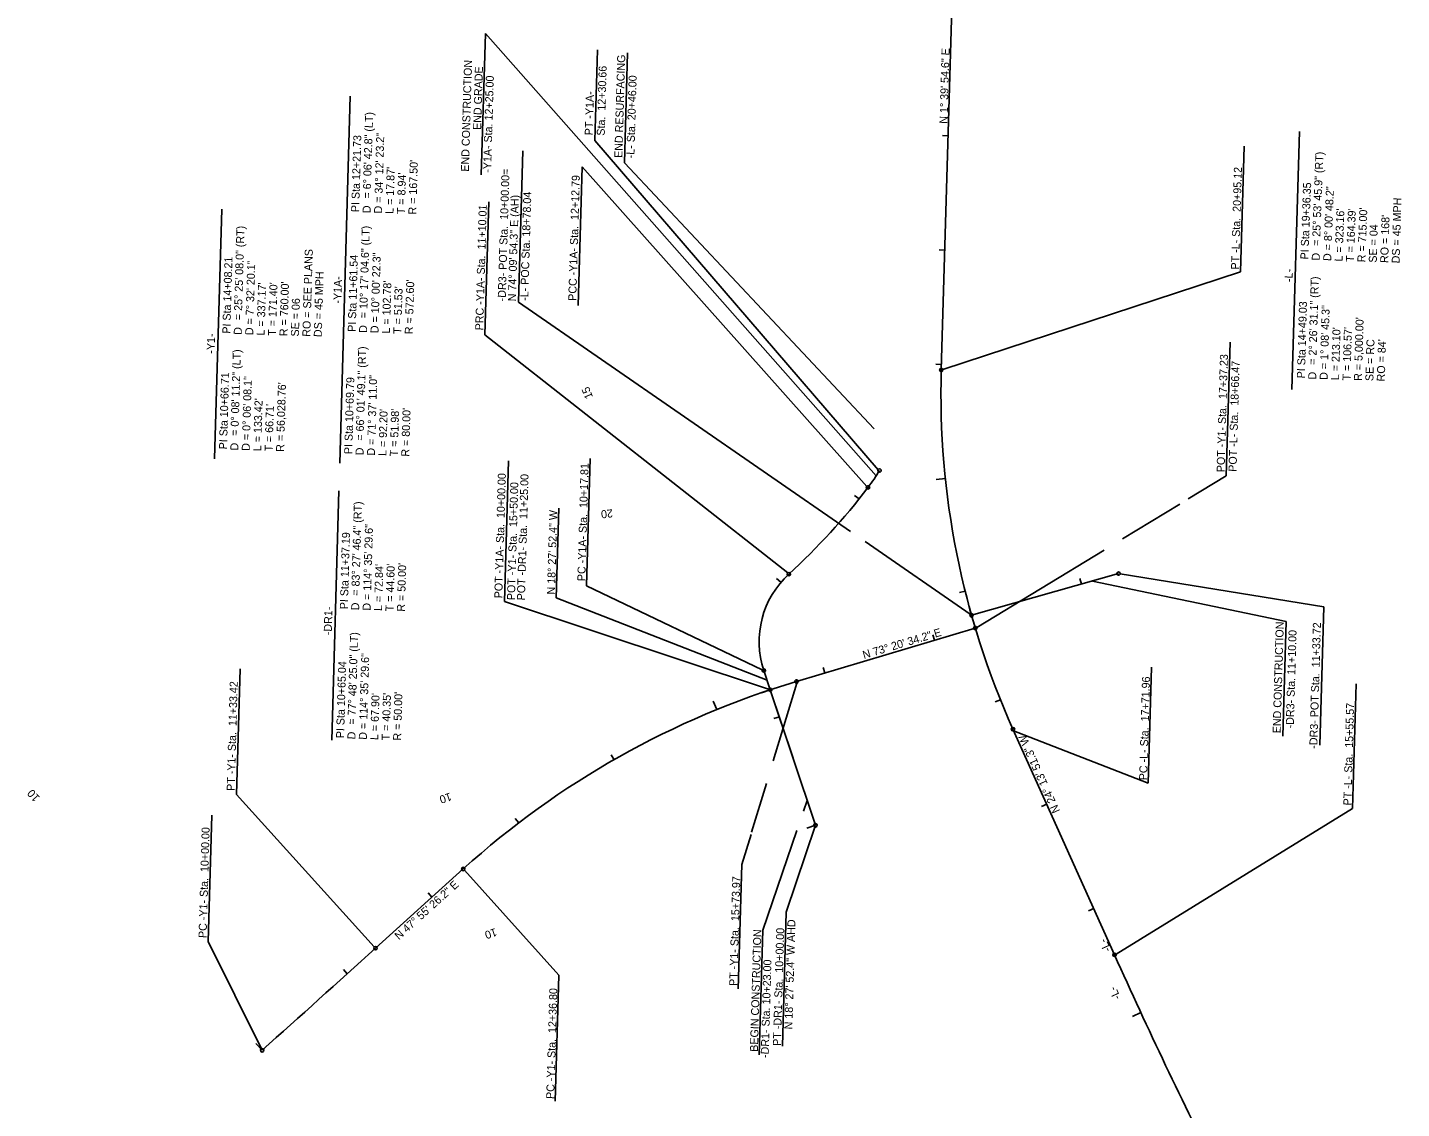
# Model space of a CAD drawing. Extents: x 2096901 to 2098386, y 684661 to 689731.
# Drawn here: x 2096901 to 2098103, y 685468 to 686414 of the extents above; entities that cross this region are included whole.
import ezdxf

# ---------------------------------------------------------------- set-up
doc = ezdxf.new("R2010")
doc.units = 0
for name, color, linetype in [('Prop Horizontal Alignment', 7, 'Continuous'), ('Prop Horizontal Alignment Curve and Spiral Data', 7, 'Continuous'), ('Prop Horizontal Alignment Direction Label', 7, 'Continuous'), ('Prop Horizontal Alignment Station Label', 7, 'Continuous'), ('Prop Horizontal Alignment Tick Label', 7, 'Continuous'), ('Prop Horizontal Alignment Tick Large', 7, 'Continuous'), ('Prop Horizontal Alignment Tick Small', 7, 'Continuous'), ('Scratch_Level_3', 7, 'Continuous'), ('Scratch_Level_5', 7, 'Continuous'), ('Scratch_Level_6', 7, 'Continuous'), ('Scratch_Level_8', 7, 'Continuous')]:
    doc.layers.add(name, color=color, linetype=linetype)

msp = doc.modelspace()

# ---------------------------------------------------------------- linework, layer by layer
at = {"layer": 'Prop Horizontal Alignment'}
for p, q in [((2097700.4, 686114.2), (2097723.2, 686897.8)), ((2097726.9, 685899.6), (2097855.5, 685936.1)), ((2097573.7, 685841.7), (2097730.1, 685888.5)), ((2097550.8, 685834.5), (2097545.2, 685851.4)), ((2097590.4, 685715.9), (2097550.8, 685834.5)), ((2097851.9, 685602.7), (2097763.1, 685800)), ((2097205.5, 685608.4), (2097282.3, 685677.7))]:
    msp.add_line(p, q, dxfattribs=at)
for centre, radius, start, end in [((2098415.1, 686093.4), 715, 178.3348, 204.2309), ((2097503.1, 686113), 167.5, 322.7189, 328.8307), ((2097180.7, 686358.3), 572.6, 312.4342, 322.7189), ((2097621.1, 685876.7), 80, 132.4342, 198.4646), ((2097791.5, 685113.6), 760, 106.6572, 132.076), ((2059659.7, 727196.1), 56028.8, 311.9396, 312.07604), ((2102411.4, 687654.7), 5000, 204.2309, 206.6729)]:
    msp.add_arc(centre, radius, start, end, dxfattribs=at)
at = {"layer": 'Prop Horizontal Alignment Curve and Spiral Data'}
for p, q in [((2097174.2, 686032.6), (2097183.5, 686353.6)), ((2098007, 686097.1), (2098013.6, 686322.8)), ((2097064.7, 686036.6), (2097071, 686254.8)), ((2097167.2, 685790.3), (2097173.5, 686008.5))]:
    msp.add_line(p, q, dxfattribs=at)
at = {"layer": 'Prop Horizontal Alignment Station Label'}
for p, q in [((2097298, 686285), (2097301.6, 686408.7)), ((2097643.4, 686021.5), (2097301.6, 686408.7)), ((2097397.3, 686315), (2097399.6, 686394.2)), ((2097423.2, 686295.3), (2097426, 686391.6)), ((2097645.1, 686027), (2097397.3, 686315)), ((2097330.7, 686173.6), (2097334.5, 686306)), ((2097962, 686200), (2097965.2, 686309.9)), ((2097382.9, 686170.5), (2097386.4, 686292)), ((2097635.2, 686012.4), (2097386.4, 686292)), ((2097641.8, 686062.8), (2097423.2, 686295.3)), ((2097301.2, 686144.9), (2097304.6, 686261.3)), ((2097701.8, 686114.6), (2097962, 686200)), ((2097621.1, 685973), (2097330.7, 686173.6)), ((2097566.1, 685936.8), (2097301.2, 686144.9)), ((2097953.1, 686138.6), (2097949.7, 686021.6)), ((2097318.4, 685911.6), (2097322, 686034.6)), ((2097390.2, 685925.5), (2097393.4, 686036.9)), ((2097916.4, 686001.4), (2097949.7, 686021.6)), ((2097363.7, 685915), (2097366, 685993.3)), ((2097858.9, 685966.4), (2097909, 685996.9)), ((2097725.8, 685900.7), (2097633.7, 685964.3)), ((2097731.5, 685889), (2097842.9, 685956.7)), ((2097857, 685935.8), (2098034.9, 685907.1)), ((2097543.8, 685852), (2097390.2, 685925.5)), ((2098002, 685894.1), (2097832.7, 685929.6)), ((2097549.4, 685835), (2097318.4, 685911.6)), ((2097548, 685842.9), (2097363.7, 685915)), ((2098031.4, 685786.1), (2098034.9, 685907.1)), ((2097999.1, 685794), (2098002, 685894.1)), ((2097084, 685743), (2097087.2, 685852.9)), ((2097881.4, 685752.7), (2097884.4, 685854.2)), ((2097574.1, 685840.3), (2097553.5, 685772.2)), ((2098060.2, 685730.7), (2098063.3, 685839.7)), ((2097762, 685799), (2097881.4, 685752.7)), ((2097547.5, 685752.5), (2097534.5, 685709.8)), ((2097204.5, 685609.5), (2097084, 685743)), ((2097583.1, 685737.7), (2097579.9, 685728.2)), ((2097853.3, 685603.3), (2098060.2, 685730.7)), ((2097062.3, 685724.7), (2097059.1, 685614.2)), ((2097590.4, 685715.9), (2097564.8, 685639.9)), ((2097534, 685708), (2097526, 685681.7)), ((2097574.1, 685711.4), (2097544.4, 685624.3)), ((2097526, 685681.7), (2097522.8, 685572.8)), ((2097283.3, 685676.6), (2097366, 685584.9)), ((2097561.4, 685522.6), (2097564.8, 685639.9)), ((2097541.2, 685515.2), (2097544.4, 685624.3)), ((2097105.9, 685520.5), (2097059.1, 685614.2)), ((2097366, 685584.9), (2097362.8, 685474.5))]:
    msp.add_line(p, q, dxfattribs=at)
for centre in [(2097700.4, 686114.2), (2097646.4, 686026.3), (2097636.3, 686011.5), (2097567.1, 685935.7), (2097855.5, 685936.1), (2097855.5, 685936.1), (2097726.9, 685899.6), (2097726.9, 685899.6), (2097730.1, 685888.5), (2097545.2, 685851.4), (2097550.8, 685834.5), (2097550.8, 685834.5), (2097550.8, 685834.5), (2097573.7, 685841.7), (2097763.1, 685800), (2097590.4, 685715.9), (2097282.3, 685677.7), (2097205.5, 685608.4), (2097851.9, 685602.7), (2097106.4, 685519.1)]:
    msp.add_circle(centre, 1.5, dxfattribs=at)
at = {"layer": 'Prop Horizontal Alignment Tick Large'}
for p, q in [((2097704, 686019.2), (2097696, 686018.4)), ((2097726.9, 685899.6), (2097724.7, 685907.3)), ((2097550.8, 685834.5), (2097543.3, 685831.9)), ((2097504, 685817.1), (2097500.9, 685824.5)), ((2097590.4, 685715.9), (2097582.8, 685713.4)), ((2097875, 685552.1), (2097867.7, 685548.8)), ((2097106.4, 685519.1), (2097101, 685525.1))]:
    msp.add_line(p, q, dxfattribs=at)
at = {"layer": 'Prop Horizontal Alignment Tick Small'}
for p, q in [((2097706.4, 686319), (2097701.4, 686319.2)), ((2097703.5, 686219.1), (2097698.5, 686219.2)), ((2097700.5, 686119.1), (2097695.6, 686119.2)), ((2097628.5, 686001.4), (2097624.6, 686004.5)), ((2097560.2, 685928.5), (2097556.4, 685931.8)), ((2097823.1, 685926.9), (2097821.7, 685931.7)), ((2097721.3, 685920.8), (2097716.4, 685919.6)), ((2097694.4, 685877.8), (2097693, 685882.6)), ((2097598.6, 685849.2), (2097597.2, 685853.9)), ((2097752.1, 685825.8), (2097747.5, 685823.9)), ((2097558.8, 685810.7), (2097554, 685809.2)), ((2097414.2, 685773.3), (2097411.7, 685777.6)), ((2097792.6, 685734.4), (2097788.1, 685732.3)), ((2097330.9, 685718), (2097327.8, 685722)), ((2097254.9, 685653), (2097251.6, 685656.7)), ((2097833.7, 685643.2), (2097829.1, 685641.1)), ((2097180.7, 685586), (2097177.4, 685589.7))]:
    msp.add_line(p, q, dxfattribs=at)
at = {"layer": 'Scratch_Level_3'}
for p, q in [((2097700.4, 686114.2), (2097723.2, 686897.8)), ((2097573.7, 685841.7), (2097730.1, 685888.5)), ((2097851.9, 685602.7), (2097763.1, 685800)), ((2097205.5, 685608.4), (2097282.3, 685677.7))]:
    msp.add_line(p, q, dxfattribs=at)
at = {"layer": 'Scratch_Level_5'}
msp.add_line((2097570.8, 685774.5), (2097550.8, 685834.5), dxfattribs=at)
for centre, radius, start, end in [((2098415.1, 686093.4), 715, 178.3348, 204.2309), ((2097791.5, 685113.6), 760, 106.6572, 132.076), ((2059659.7, 727196.1), 56028.8, 311.9396, 312.07604), ((2102411.4, 687654.7), 5000, 204.2309, 206.6729)]:
    msp.add_arc(centre, radius, start, end, dxfattribs=at)
at = {"layer": 'Scratch_Level_6'}
msp.add_line((2097545.2, 685851.4), (2097550.8, 685834.5), dxfattribs=at)
for centre, radius, start, end in [((2097503.1, 686113), 167.5, 322.7189, 328.8307), ((2097180.7, 686358.3), 572.6, 312.4342, 322.7189), ((2097621.1, 685876.7), 80, 132.4342, 198.4646)]:
    msp.add_arc(centre, radius, start, end, dxfattribs=at)
at = {"layer": 'Scratch_Level_8'}
msp.add_line((2097726.9, 685899.6), (2097855.5, 685936.1), dxfattribs=at)

# ---------------------------------------------------------------- texts
at = {"layer": 'Prop Horizontal Alignment Curve and Spiral Data'}
for s, rotation, p in [('= 6%%d 06\' 42.8" (LT)', 88.3348, (2097201.3, 686264.1)), ('PI Sta 12+21.73', 88.3348, (2097191.2, 686252.2)), ('D = 34%%d 12\' 23.2"', 88.3348, (2097211.2, 686251)), ('= 25%%d 53\' 45.9" (RT)', 87.8037, (2098031.6, 686222.6)), ("L = 17.87'", 88.3348, (2097221.2, 686250.7)), ("R = 167.50'", 88.3348, (2097241.2, 686250.1)), ("T = 8.94'", 88.3348, (2097231.2, 686250.4)), ('PI Sta 19+36.35', 87.8037, (2098021.4, 686210.8)), ('D = 8%%d 00\' 48.2"', 87.8037, (2098041.4, 686209.4)), ('D', 88.3348, (2097201.2, 686251.3)), ("L = 323.16'", 87.8037, (2098051.3, 686209)), ("T = 164.39'", 87.8037, (2098061.3, 686208.6)), ("R = 715.00'", 87.8037, (2098071.3, 686208.3)), ('DS = 45 MPH', 88.3348, (2098101.3, 686207.4)), ("RO = 168'", 88.3348, (2098091.3, 686207.7)), ('= 25%%d 25\' 08.0" (RT)', 88.3348, (2097088.6, 686157.8)), ('= 10%%d 17\' 04.6" (LT)', 88.3348, (2097198.2, 686159.4)), ('SE = 04', 88.3348, (2098081.3, 686208)), ('RO = SEE PLANS', 88.3348, (2097148.5, 686143.2)), ('PI Sta 14+08.21', 88.3348, (2097078.5, 686145.9)), ('D = 7%%d 32\' 20.1"', 88.3348, (2097098.5, 686144.6)), ('PI Sta 11+61.54', 88.3348, (2097188.2, 686147.5)), ('D = 10%%d 00\' 22.3"', 88.3348, (2097208.1, 686146.3)), ('D', 87.8037, (2098031.4, 686209.8)), ('DS = 45 MPH', 88.3348, (2097158.5, 686142.9)), ('-Y1A-', 88.3348, (2097175.6, 686172.2)), ('-L-', 88.3348, (2098007.6, 686191.1)), ('= 2%%d 26\' 31.1" (RT)', 88.3348, (2098028.4, 686118.7)), ("L = 337.17'", 88.3348, (2097108.5, 686144.3)), ("T = 171.40'", 88.3348, (2097118.5, 686144)), ("R = 760.00'", 88.3348, (2097128.5, 686143.7)), ("L = 102.78'", 88.3348, (2097218.1, 686146)), ("T = 51.53'", 88.3348, (2097228.1, 686145.7)), ("R = 572.60'", 88.3348, (2097238.1, 686145.4)), ('SE = 06', 88.3348, (2097138.5, 686143.4)), ('PI Sta 14+49.03', 88.3348, (2098018.4, 686106.8)), ('D = 1%%d 08\' 45.3"', 88.3348, (2098038.3, 686105.5)), ("R = 5,000.00'", 88.3348, (2098068.3, 686104.6)), ('D', 88.3348, (2097088.5, 686144.9)), ('D', 88.3348, (2097198.1, 686146.6)), ("L = 213.10'", 88.3348, (2098048.3, 686105.2)), ("T = 106.57'", 88.3348, (2098058.3, 686104.9)), ('-Y1-', 88.3348, (2097064.8, 686128.4)), ('= 66%%d 01\' 49.1" (RT)', 88.3348, (2097195.1, 686052.3)), ('SE = RC', 88.3348, (2098078.3, 686104.4)), ("RO = 84'", 88.3348, (2098088.3, 686104.1)), ('= 0%%d 08\' 11.2" (LT)', 88.3348, (2097085.6, 686056.5)), ('PI Sta 10+66.71', 88.3348, (2097075.6, 686044.7)), ('D', 88.3348, (2098028.3, 686105.8)), ('D = 0%%d 06\' 08.1"', 88.3348, (2097095.5, 686043.4)), ("R = 56,028.76'", 88.3348, (2097125.5, 686042.5)), ('PI Sta 10+69.79', 88.3348, (2097185.1, 686040.5)), ('D = 71%%d 37\' 11.0"', 88.3348, (2097205, 686039.2)), ("L = 133.42'", 88.3348, (2097105.5, 686043.1)), ("T = 66.71'", 88.3348, (2097115.5, 686042.8)), ("L = 92.20'", 88.3348, (2097215, 686038.9)), ("T = 51.98'", 88.3348, (2097225, 686038.6)), ("R = 80.00'", 88.3348, (2097235, 686038.3)), ('D', 88.3348, (2097085.5, 686043.7)), ('D', 88.3348, (2097195, 686039.5)), ('= 83%%d 27\' 46.4" (RT)', 88.3348, (2097191.3, 685916.7)), ('D = 114%%d 35\' 29.6"', 88.3348, (2097201.2, 685903.6)), ('PI Sta 11+37.19', 88.3348, (2097181.3, 685904.8)), ("L = 72.84'", 88.3348, (2097211.2, 685903.3)), ("T = 44.60'", 88.3348, (2097221.2, 685903)), ("R = 50.00'", 88.3348, (2097231.2, 685902.7)), ('-DR1-', 88.3348, (2097167.2, 685882.1)), ('D', 88.3348, (2097191.2, 685903.9)), ('= 77%%d 48\' 25.0" (LT)', 88.3348, (2097188, 685803.9)), ('PI Sta 10+65.04', 88.3348, (2097178, 685792)), ('D = 114%%d 35\' 29.6"', 88.3348, (2097197.9, 685790.7)), ("L = 67.90'", 88.3348, (2097207.9, 685790.4)), ("T = 40.35'", 88.3348, (2097217.9, 685790.1)), ("R = 50.00'", 88.3348, (2097227.9, 685789.9)), ('D', 88.3348, (2097187.9, 685791))]:
    msp.add_text(s, height=7, rotation=rotation, dxfattribs=at).set_placement(p)
at = {"layer": 'Prop Horizontal Alignment Direction Label'}
for s, rotation, p in [('N 1%%d 39\' 54.6" E', 88.3348, (2097705.8, 686329.5)), ('N 74%%d 09\' 54.3" E (AH)', 88.3348, (2097328.3, 686174.2)), ('N 18%%d 27\' 52.4" W', 88.3348, (2097362.5, 685917.7)), ('N 73%%d 20\' 34.2" E', 16.6572, (2097632.8, 685861.4)), ('N 24%%d 13\' 51.3" W', 114.2309, (2097804.4, 685728.5)), ('N 47%%d 55\' 26.2" E', 42.076, (2097226, 685615.3)), ('N 18%%d 27\' 52.4" W AHD', 88.3348, (2097570.1, 685537.3))]:
    msp.add_text(s, height=7, rotation=rotation, dxfattribs=at).set_placement(p)
at = {"layer": 'Prop Horizontal Alignment Station Label'}
for s, rotation, p in [('END RESURFACING', 88.3348, (2097421.4, 686299.6)), ('END CONSTRUCTION', 88.3348, (2097287.2, 686287.6)), ('END GRADE', 88.3348, (2097297.9, 686324.1)), ('Sta.  12+30.66', 88.3348, (2097406, 686319.1)), ('-Y1A- Sta. 12+25.00', 88.3348, (2097306.6, 686286.6)), ('-L- Sta. 20+46.00', 88.3348, (2097431.9, 686299.3)), ('PT -Y1A-', 88.3348, (2097395.5, 686319.4)), ('PT -L- Sta.  20+95.12', 88.3348, (2097960.8, 686202)), ('-DR3- POT Sta.  10+00.00=', 88.3348, (2097319.4, 686174.2)), ('PCC -Y1A- Sta.  12+12.79', 88.3348, (2097381.1, 686174.6)), ('-L- POC Sta. 18+78.04', 88.3348, (2097339.1, 686174.6)), ('PRC -Y1A- Sta.  11+10.01', 88.3348, (2097299.7, 686148.8)), ('POT -Y1- Sta.  17+37.23', 88.3348, (2097948.2, 686024.7)), ('POT -L- Sta.  18+66.47', 88.3348, (2097958.6, 686025.1)), ('PC -Y1A- Sta.  10+17.81', 88.3348, (2097389, 685929.4)), ('POT -Y1A- Sta.  10+00.00', 88.3348, (2097316.4, 685914.4)), ('POT -Y1- Sta.  15+50.00', 88.3348, (2097327.5, 685912.8)), ('POT -DR1- Sta.  11+25.00', 88.3348, (2097336.2, 685912.6)), ('END CONSTRUCTION', 88.3348, (2097997.2, 685796.3)), ('-DR3- Sta. 11+10.00', 88.3348, (2098008.7, 685800.6)), ('-DR3- POT Sta.  11+33.72', 88.3348, (2098029.3, 685782.8)), ('PT -Y1- Sta.  11+33.42', 88.3348, (2097082.3, 685745.9)), ('PC -L- Sta.  17+71.96', 88.3348, (2097880.4, 685755.2)), ('PT -L- Sta.  15+55.57', 88.3348, (2098059, 685733.2)), ('PC -Y1- Sta.  10+00.00', 88.3348, (2097057.7, 685617.2)), ('PT -Y1- Sta.  15+73.97', 88.3348, (2097521.9, 685575.3)), ('BEGIN CONSTRUCTION', 88.3348, (2097540, 685517.7)), ('PT -DR1- Sta.  10+00.00', 88.3348, (2097560.1, 685522.9)), ('-L-', 114.4674, (2097849.1, 685607)), ('-DR1- Sta. 10+23.00', 88.3348, (2097549.4, 685512.3)), ('PC -Y1- Sta.  12+36.80', 88.3348, (2097361.8, 685476.4)), ('-L-', 114.4674, (2097857.5, 685565.2))]:
    msp.add_text(s, height=7, rotation=rotation, dxfattribs=at).set_placement(p)
at = {"layer": 'Prop Horizontal Alignment Tick Label'}
for s, rotation, p in [('15', 112.234, (2097395.9, 686090.6)), ('20', 185.957, (2097412.8, 685992.4)), ('10', 131.9396, (2096912.4, 685740.3)), ('10', 198.4646, (2097270.7, 685744.6)), ('10', 198.4646, (2097310.3, 685626.1))]:
    msp.add_text(s, height=7, rotation=rotation, dxfattribs=at).set_placement(p)

doc.saveas('drawing.dxf')
